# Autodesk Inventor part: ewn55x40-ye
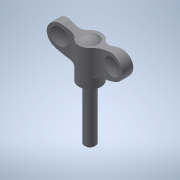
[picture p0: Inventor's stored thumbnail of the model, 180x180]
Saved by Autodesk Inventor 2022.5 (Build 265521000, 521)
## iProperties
Created: 2016-12
Part Number: ewn55x40-ye
Material: 一般
Document SubType Name: Modeling
Designer: imaocorp
Density: 1 g/cm^3
Appearance: 既定
Author: imaocorp
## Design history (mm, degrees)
node "ewn55x40-ye.x_t1"
node "ewn55x40-ye"
node "Base1"
